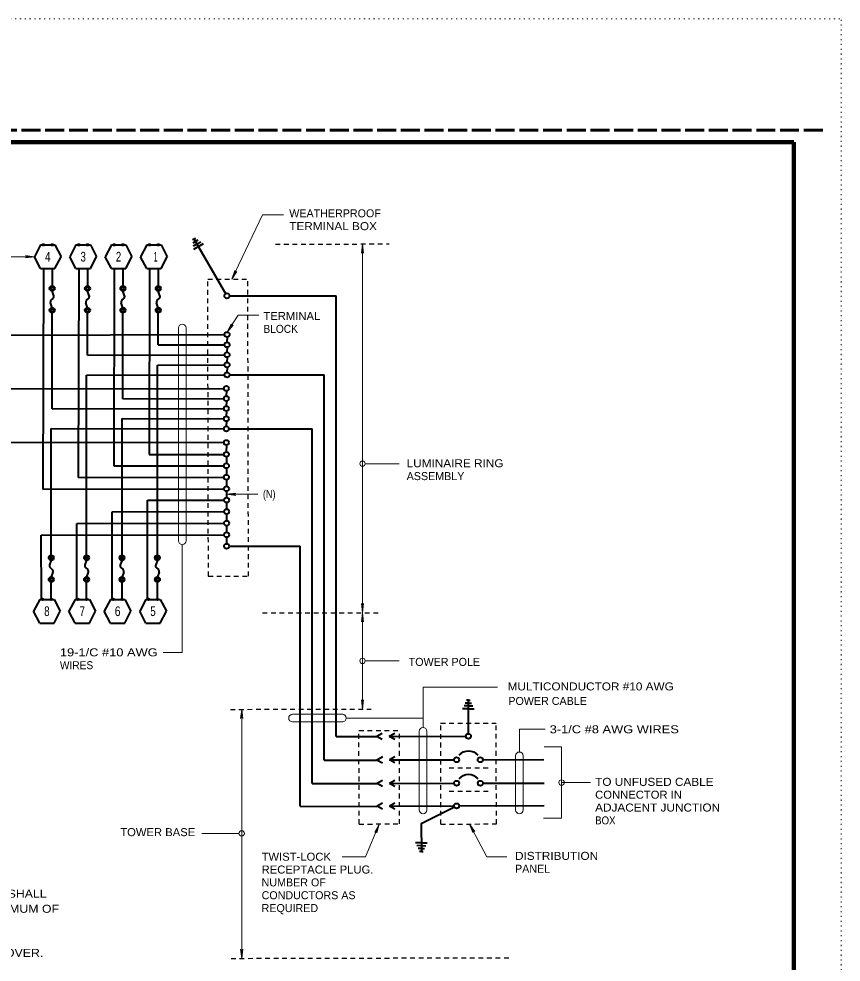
# Model space of a CAD drawing. Extents: x 312583 to 312854, y 144419 to 144597.
# Drawn here: x 312775.4 to 312853.5, y 144507.2 to 144596.8 of the extents above; entities that cross this region are included whole.
import ezdxf
from ezdxf.enums import TextEntityAlignment as Align

# ---------------------------------------------------------------- set-up
doc = ezdxf.new("R2010")
doc.units = 0
doc.header["$LTSCALE"] = 0.3
doc.header["$PDMODE"] = 32
doc.header["$PDSIZE"] = 0.15
for name, pattern in [('DOTTED', [1.5, 0.3, -1.2]), ('LONG_DASHED', [7.5, 6, -1.5]), ('SHORT_DASHED', [2.7, 1.5, -1.2])]:
    doc.linetypes.add(name, pattern=pattern)
for name, color, linetype, lineweight in [('1', 7, 'Continuous', 40), ('2', 7, 'Continuous', 13), ('62', 7, 'DOTTED', 13), ('63', 7, 'LONG_DASHED', 60)]:
    doc.layers.add(name, color=color, linetype=linetype, lineweight=lineweight)

msp = doc.modelspace()

# ---------------------------------------------------------------- linework, layer by layer
at = {"layer": '1', "lineweight": 158}
msp.add_line((312849, 144423.1446), (312849, 144585.0846), dxfattribs=at)
at = {"layer": '1'}
for p, q in [((312777.5006, 144575.328), (312776.918, 144574.201)), ((312777.5006, 144575.328), (312778.8653, 144575.328)), ((312778.8653, 144575.328), (312779.448, 144574.201)), ((312780.8586, 144575.328), (312780.276, 144574.201)), ((312780.8586, 144575.328), (312782.2233, 144575.328)), ((312782.2233, 144575.328), (312782.806, 144574.201)), ((312784.2166, 144575.328), (312783.634, 144574.201)), ((312784.2166, 144575.328), (312785.5813, 144575.328)), ((312785.5813, 144575.328), (312786.164, 144574.201)), ((312787.5746, 144575.328), (312786.992, 144574.201)), ((312787.5746, 144575.328), (312788.9393, 144575.328)), ((312788.9393, 144575.328), (312789.522, 144574.201)), ((312792.0826, 144575.88), (312791.9293, 144575.788)), ((312792.213, 144575.6576), (312791.9523, 144575.4966)), ((312792.351, 144575.4046), (312791.983, 144575.1976)), ((312792.489, 144575.1746), (312792.006, 144574.8986)), ((312792.0826, 144575.88), (312792.2283, 144575.9643)), ((312795.0726, 144570.6896), (312792.0826, 144575.88)), ((312792.213, 144575.6576), (312792.4736, 144575.788)), ((312792.3586, 144575.4123), (312792.719, 144575.6193)), ((312792.489, 144575.1746), (312792.9566, 144575.4506)), ((312777.5006, 144573.074), (312776.918, 144574.201)), ((312778.8653, 144573.074), (312779.448, 144574.201)), ((312780.8586, 144573.074), (312780.276, 144574.201)), ((312782.2233, 144573.074), (312782.806, 144574.201)), ((312784.2166, 144573.074), (312783.634, 144574.201)), ((312785.5813, 144573.074), (312786.164, 144574.201)), ((312787.5746, 144573.074), (312786.992, 144574.201)), ((312788.9393, 144573.074), (312789.522, 144574.201)), ((312777.5006, 144573.074), (312778.8653, 144573.074)), ((312777.769, 144573.074), (312777.7153, 144552.1363)), ((312778.597, 144573.074), (312778.597, 144571.4256)), ((312780.8586, 144573.074), (312782.2233, 144573.074)), ((312781.127, 144573.074), (312781.081, 144553.2326)), ((312781.955, 144573.074), (312781.955, 144571.4256)), ((312784.2166, 144573.074), (312785.5813, 144573.074)), ((312784.485, 144573.074), (312784.4466, 144554.329)), ((312785.313, 144573.074), (312785.313, 144571.4256)), ((312787.5746, 144573.074), (312788.9393, 144573.074)), ((312787.843, 144573.074), (312787.797, 144555.4253)), ((312788.671, 144573.074), (312788.671, 144571.4256)), ((312778.758, 144570.498), (312778.597, 144570.9503)), ((312782.116, 144570.498), (312781.955, 144570.9503)), ((312785.474, 144570.498), (312785.313, 144570.9503)), ((312788.832, 144570.498), (312788.671, 144570.9503)), ((312778.597, 144569.3556), (312778.436, 144569.808)), ((312778.4973, 144570.061), (312778.6966, 144570.245)), ((312781.955, 144569.3556), (312781.794, 144569.808)), ((312781.8553, 144570.061), (312782.0546, 144570.245)), ((312785.313, 144569.3556), (312785.152, 144569.808)), ((312785.2133, 144570.061), (312785.4126, 144570.245)), ((312788.671, 144569.3556), (312788.51, 144569.808)), ((312788.5713, 144570.061), (312788.7706, 144570.245)), ((312795.433, 144570.4826), (312805.576, 144570.498)), ((312805.576, 144528.6303), (312805.576, 144570.498)), ((312778.597, 144559.7493), (312778.597, 144568.8803)), ((312781.955, 144564.8553), (312781.955, 144568.8803)), ((312785.313, 144560.7076), (312785.313, 144568.8803)), ((312788.671, 144565.829), (312788.671, 144568.8803)), ((312770.7003, 144566.749), (312794.9653, 144566.8026)), ((312795.203, 144566.565), (312795.1953, 144566.082)), ((312788.671, 144565.829), (312794.9653, 144565.8443)), ((312795.203, 144565.6066), (312795.1953, 144565.1236)), ((312781.955, 144564.8553), (312794.9653, 144564.886)), ((312795.203, 144564.6483), (312795.1953, 144564.1653)), ((312788.5866, 144563.9123), (312794.9653, 144563.9276)), ((312788.5866, 144545.8573), (312788.5866, 144563.9123)), ((312795.203, 144563.69), (312795.1953, 144563.207)), ((312781.8706, 144562.9386), (312794.9653, 144562.9693)), ((312781.8706, 144545.8573), (312781.8706, 144562.9386)), ((312795.4406, 144562.9693), (312804.4336, 144562.9846)), ((312804.4336, 144526.3916), (312804.4336, 144562.9846)), ((312770.708, 144561.6353), (312794.8963, 144561.689)), ((312795.134, 144561.4513), (312795.1263, 144560.9683)), ((312785.313, 144560.7076), (312794.8963, 144560.7306)), ((312795.134, 144560.493), (312795.1263, 144560.01)), ((312778.597, 144559.7493), (312794.8963, 144559.7723)), ((312795.134, 144559.5346), (312795.1263, 144559.0516)), ((312785.2286, 144545.8573), (312785.2286, 144558.837)), ((312785.2286, 144558.837), (312794.8963, 144558.814)), ((312795.134, 144558.5763), (312795.1263, 144558.0933)), ((312778.5126, 144545.8573), (312778.5126, 144557.894)), ((312778.5126, 144557.894), (312794.8963, 144557.8556)), ((312795.3716, 144557.8556), (312803.2836, 144557.8633)), ((312803.2836, 144524.1683), (312803.2836, 144557.8633)), ((312770.616, 144556.5983), (312794.8963, 144556.5446)), ((312787.797, 144555.4253), (312794.904, 144555.433)), ((312795.134, 144556.307), (312795.1263, 144555.6706)), ((312795.1416, 144555.1953), (312795.134, 144554.559)), ((312784.4466, 144554.329), (312794.904, 144554.3443)), ((312795.1416, 144554.1066), (312795.134, 144553.4703)), ((312781.081, 144553.2326), (312794.904, 144553.2556)), ((312795.1416, 144553.018), (312795.134, 144552.3816)), ((312777.7153, 144552.1363), (312794.9116, 144552.167)), ((312795.1493, 144551.9293), (312795.1416, 144551.3236)), ((312787.636, 144551.0706), (312794.9193, 144551.086)), ((312787.659, 144541.6636), (312787.636, 144551.0706)), ((312795.157, 144550.8483), (312795.1493, 144550.212)), ((312784.2856, 144549.9743), (312794.9193, 144549.9896)), ((312784.301, 144541.6636), (312784.2856, 144549.9743)), ((312795.157, 144549.752), (312795.1493, 144549.1156)), ((312780.9276, 144548.8703), (312794.9193, 144548.8933)), ((312780.943, 144541.6636), (312780.9276, 144548.8703)), ((312795.157, 144548.6556), (312795.1493, 144548.0193)), ((312777.5696, 144547.7663), (312794.9193, 144547.797)), ((312777.585, 144541.6636), (312777.5696, 144547.7663)), ((312795.157, 144547.5593), (312795.1493, 144546.923)), ((312795.4866, 144546.7006), (312802.1336, 144546.7083)), ((312802.1336, 144522.014), (312802.1336, 144546.7083)), ((312778.5126, 144545.382), (312778.3516, 144544.9296)), ((312781.8706, 144545.382), (312781.7096, 144544.9296)), ((312785.2286, 144545.382), (312785.0676, 144544.9296)), ((312788.5866, 144545.382), (312788.4256, 144544.9296)), ((312778.413, 144544.6766), (312778.6123, 144544.4926)), ((312778.6736, 144544.2396), (312778.5126, 144543.7873)), ((312781.771, 144544.6766), (312781.9703, 144544.4926)), ((312782.0316, 144544.2396), (312781.8706, 144543.7873)), ((312785.129, 144544.6766), (312785.3283, 144544.4926)), ((312785.3896, 144544.2396), (312785.2286, 144543.7873)), ((312788.487, 144544.6766), (312788.6863, 144544.4926)), ((312788.7476, 144544.2396), (312788.5866, 144543.7873)), ((312778.5126, 144541.6636), (312778.5126, 144543.312)), ((312781.8706, 144541.6636), (312781.8706, 144543.312)), ((312785.2286, 144541.6636), (312785.2286, 144543.312)), ((312788.5866, 144541.6636), (312788.5866, 144543.312)), ((312777.4163, 144541.6636), (312776.8336, 144540.5366)), ((312777.4163, 144541.6636), (312778.781, 144541.6636)), ((312778.781, 144541.6636), (312779.3636, 144540.5366)), ((312780.7743, 144541.6636), (312780.1916, 144540.5366)), ((312780.7743, 144541.6636), (312782.139, 144541.6636)), ((312782.139, 144541.6636), (312782.7216, 144540.5366)), ((312784.1323, 144541.6636), (312783.5496, 144540.5366)), ((312784.1323, 144541.6636), (312785.497, 144541.6636)), ((312785.497, 144541.6636), (312786.0796, 144540.5366)), ((312787.4903, 144541.6636), (312786.9076, 144540.5366)), ((312787.4903, 144541.6636), (312788.855, 144541.6636)), ((312788.855, 144541.6636), (312789.4376, 144540.5366)), ((312777.4163, 144539.4096), (312776.8336, 144540.5366)), ((312778.781, 144539.4096), (312779.3636, 144540.5366)), ((312780.7743, 144539.4096), (312780.1916, 144540.5366)), ((312782.139, 144539.4096), (312782.7216, 144540.5366)), ((312784.1323, 144539.4096), (312783.5496, 144540.5366)), ((312785.497, 144539.4096), (312786.0796, 144540.5366)), ((312787.4903, 144539.4096), (312786.9076, 144540.5366)), ((312788.855, 144539.4096), (312789.4376, 144540.5366)), ((312777.4163, 144539.4096), (312778.781, 144539.4096)), ((312780.7743, 144539.4096), (312782.139, 144539.4096)), ((312784.1323, 144539.4096), (312785.497, 144539.4096)), ((312787.4903, 144539.4096), (312788.855, 144539.4096)), ((312818.1186, 144531.2676), (312817.5666, 144531.2753)), ((312818.111, 144531.536), (312817.697, 144531.5436)), ((312818.1186, 144531.8196), (312817.8196, 144531.812)), ((312818.1186, 144532.088), (312817.9423, 144532.0803)), ((312818.1186, 144528.8986), (312818.1186, 144532.088)), ((312818.1186, 144532.088), (312818.295, 144532.0803)), ((312818.1186, 144531.8196), (312818.4176, 144531.812)), ((312818.1186, 144531.2676), (312818.6706, 144531.2753)), ((312818.1263, 144531.536), (312818.5403, 144531.5436)), ((312805.576, 144528.6303), (312809.4246, 144528.638)), ((312809.9383, 144528.9293), (312809.4246, 144528.638)), ((312809.9383, 144528.3466), (312809.4246, 144528.638)), ((312811.119, 144528.937), (312810.6053, 144528.6456)), ((312810.6053, 144528.6456), (312817.881, 144528.661)), ((312811.119, 144528.3543), (312810.6053, 144528.6456)), ((312804.4336, 144526.3916), (312809.4323, 144526.407)), ((312809.946, 144526.6983), (312809.4323, 144526.407)), ((312809.946, 144526.1156), (312809.4323, 144526.407)), ((312811.1266, 144526.706), (312810.613, 144526.4146)), ((312810.613, 144526.4146), (312816.754, 144526.43)), ((312811.1266, 144526.1233), (312810.613, 144526.4146)), ((312819.4833, 144526.43), (312825.287, 144526.453)), ((312803.2836, 144524.1683), (312809.44, 144524.1836)), ((312809.9536, 144524.4673), (312809.44, 144524.176)), ((312809.9536, 144523.8846), (312809.44, 144524.176)), ((312811.1343, 144524.475), (312810.6206, 144524.1836)), ((312810.6206, 144524.1836), (312816.7616, 144524.199)), ((312811.1343, 144523.8923), (312810.6206, 144524.1836)), ((312819.491, 144524.199), (312825.2946, 144524.222)), ((312809.9536, 144522.313), (312809.44, 144522.0216)), ((312811.1343, 144522.3206), (312810.6206, 144522.0293)), ((312802.1336, 144522.014), (312809.4323, 144521.991)), ((312809.9536, 144521.7303), (312809.44, 144522.0216)), ((312810.6206, 144522.0293), (312816.7616, 144522.0446)), ((312811.1343, 144521.738), (312810.6206, 144522.0293)), ((312817.237, 144522.0446), (312825.31, 144522.0753)), ((312813.649, 144518.541), (312813.097, 144518.5333)), ((312813.6413, 144518.2726), (312813.2273, 144518.265)), ((312813.649, 144517.989), (312813.35, 144517.9966)), ((312813.649, 144518.541), (312814.201, 144518.5333)), ((312813.649, 144517.989), (312813.948, 144517.9966)), ((312813.6566, 144518.2726), (312814.0706, 144518.265)), ((312813.649, 144517.7206), (312813.4726, 144517.7283)), ((312813.649, 144517.7206), (312813.8253, 144517.7283))]:
    msp.add_line(p, q, dxfattribs=at)
at = {"layer": '1', "linetype": 'SHORT_DASHED', "lineweight": 25}
for p, q in [((312799.7953, 144575.3893), (312810.5823, 144575.4123)), ((312793.3706, 144572.062), (312797.1733, 144572.0696)), ((312793.432, 144543.864), (312793.3706, 144572.062)), ((312797.2346, 144543.8716), (312797.1733, 144572.0696)), ((312793.4243, 144543.864), (312797.227, 144543.8716)), ((312798.5686, 144540.368), (312809.7773, 144540.391)), ((312795.525, 144531.214), (312808.8726, 144531.2446)), ((312815.4813, 144529.8953), (312820.756, 144529.903)), ((312815.4966, 144520.3196), (312815.4813, 144529.8953)), ((312820.7713, 144520.335), (312820.756, 144529.903)), ((312807.7226, 144529.1976), (312811.5636, 144529.2053)), ((312807.738, 144520.3273), (312807.7226, 144529.1976)), ((312811.579, 144520.335), (312811.5636, 144529.2053)), ((312816.2863, 144525.6633), (312820.0046, 144525.6633)), ((312816.294, 144523.4323), (312820.0123, 144523.4323)), ((312807.738, 144520.3273), (312811.579, 144520.335)), ((312815.4966, 144520.3196), (312820.7713, 144520.335)), ((312795.5786, 144507.57), (312822.159, 144507.6313))]:
    msp.add_line(p, q, dxfattribs=at)
at = {"layer": '1', "lineweight": 158}
msp.add_lwpolyline([(312616.5, 144423.1446), (312616.5, 144585.0846), (312849, 144585.0846)], dxfattribs=at)
at = {"layer": '1'}
msp.add_lwpolyline([(312816.7846, 144521.9373), (312813.6413, 144520.358), (312813.649, 144517.7206)], dxfattribs=at)
for centre, radius in [((312778.597, 144571.188), 0.2396), ((312778.597, 144571.188), 0.1198), ((312781.955, 144571.188), 0.2396), ((312781.955, 144571.188), 0.1198), ((312785.313, 144571.188), 0.2396), ((312785.313, 144571.188), 0.1198), ((312788.671, 144571.188), 0.2396), ((312788.671, 144571.188), 0.1198), ((312795.1928, 144570.4855), 0.2396), ((312778.597, 144569.118), 0.2396), ((312778.597, 144569.118), 0.1198), ((312781.955, 144569.118), 0.2396), ((312781.955, 144569.118), 0.1198), ((312785.313, 144569.118), 0.2396), ((312785.313, 144569.118), 0.1198), ((312788.671, 144569.118), 0.2396), ((312788.671, 144569.118), 0.1198), ((312795.203, 144566.8026), 0.2396), ((312795.203, 144565.8443), 0.2396), ((312795.203, 144564.886), 0.2396), ((312795.203, 144563.9276), 0.2396), ((312795.203, 144562.9693), 0.2396), ((312795.134, 144561.689), 0.2396), ((312795.134, 144560.7306), 0.2396), ((312795.134, 144559.7723), 0.2396), ((312795.134, 144558.814), 0.2396), ((312795.134, 144557.8556), 0.2396), ((312795.134, 144556.5446), 0.2396), ((312795.1416, 144555.433), 0.2396), ((312795.1416, 144554.3443), 0.2396), ((312795.1416, 144553.2556), 0.2396), ((312795.1493, 144552.167), 0.2396), ((312795.157, 144551.086), 0.2396), ((312795.157, 144549.9896), 0.2396), ((312795.157, 144548.8933), 0.2396), ((312795.157, 144547.797), 0.2396), ((312795.157, 144546.7006), 0.2396), ((312778.5126, 144545.6196), 0.2396), ((312778.5126, 144545.6196), 0.1198), ((312781.8706, 144545.6196), 0.2396), ((312781.8706, 144545.6196), 0.1198), ((312785.2286, 144545.6196), 0.2396), ((312785.2286, 144545.6196), 0.1198), ((312788.5866, 144545.6196), 0.2396), ((312788.5866, 144545.6196), 0.1198), ((312778.5126, 144543.5496), 0.2396), ((312781.8706, 144543.5496), 0.2396), ((312785.2286, 144543.5496), 0.2396), ((312788.5866, 144543.5496), 0.2396), ((312778.5126, 144543.5496), 0.1198), ((312781.8706, 144543.5496), 0.1198), ((312785.2286, 144543.5496), 0.1198), ((312788.5866, 144543.5496), 0.1198), ((312818.1186, 144528.661), 0.2396), ((312816.9916, 144526.43), 0.2396), ((312819.2456, 144526.43), 0.2396), ((312816.9993, 144524.199), 0.2396), ((312819.2533, 144524.199), 0.2396), ((312816.9993, 144522.0446), 0.2396)]:
    msp.add_circle(centre, radius, dxfattribs=at)
for centre, radius, start, end in [((312778.6612, 144569.8857), 0.2396, 132.8789, 199.74684), ((312778.5326, 144570.4204), 0.2396, 312.82526, 19.74684), ((312782.0192, 144569.8857), 0.2396, 132.8789, 199.74684), ((312781.8906, 144570.4204), 0.2396, 312.82526, 19.74684), ((312785.3772, 144569.8857), 0.2396, 132.8789, 199.74684), ((312785.2486, 144570.4204), 0.2396, 312.82526, 19.74684), ((312788.7352, 144569.8857), 0.2396, 132.8789, 199.74684), ((312788.6066, 144570.4204), 0.2396, 312.82526, 19.74684), ((312778.5769, 144544.8519), 0.2396, 160.25316, 227.1211), ((312781.9349, 144544.8519), 0.2396, 160.25316, 227.1211), ((312785.2929, 144544.8519), 0.2396, 160.25316, 227.1211), ((312788.6509, 144544.8519), 0.2396, 160.25316, 227.1211), ((312778.4483, 144544.3172), 0.2396, 340.25316, 47.17474), ((312781.8063, 144544.3172), 0.2396, 340.25316, 47.17474), ((312785.1643, 144544.3172), 0.2396, 340.25316, 47.17474), ((312788.5223, 144544.3172), 0.2396, 340.25316, 47.17474), ((312818.1186, 144525.9717), 1.2786, 43.48857, 136.51143), ((312818.1263, 144523.7407), 1.2786, 43.48857, 136.51143)]:
    msp.add_arc(centre, radius, start, end, dxfattribs=at)
for p in [(312777.769, 144575.328), (312778.597, 144575.328), (312781.127, 144575.328), (312781.955, 144575.328), (312784.485, 144575.328), (312785.313, 144575.328), (312787.843, 144575.328), (312788.671, 144575.328), (312777.6846, 144541.6636), (312778.5126, 144541.6636), (312781.0426, 144541.6636), (312781.8706, 144541.6636), (312784.4006, 144541.6636), (312785.2286, 144541.6636), (312787.7586, 144541.6636), (312788.5866, 144541.6636)]:
    msp.add_point(p, dxfattribs=at)
at = {"layer": '2'}
for p, q in [((312798.5686, 144578.1876), (312795.663, 144572.0696)), ((312798.5686, 144578.1876), (312800.5466, 144578.1876)), ((312808.06, 144575.4123), (312807.9526, 144574.546)), ((312808.06, 144540.391), (312808.06, 144575.4123)), ((312808.06, 144575.4123), (312808.1673, 144574.546)), ((312776.0516, 144574.3083), (312776.3276, 144574.201)), ((312776.918, 144574.201), (312776.0516, 144574.3083)), ((312807.9526, 144574.546), (312808.06, 144574.822)), ((312808.1673, 144574.546), (312808.06, 144574.822)), ((312773.33, 144574.201), (312776.918, 144574.201)), ((312776.0516, 144574.0936), (312776.3276, 144574.201)), ((312776.918, 144574.201), (312776.0516, 144574.0936)), ((312795.663, 144572.0696), (312795.939, 144572.8976)), ((312795.663, 144572.0696), (312796.1306, 144572.8056)), ((312795.939, 144572.8976), (312795.916, 144572.6063)), ((312796.1306, 144572.8056), (312795.916, 144572.6063)), ((312796.2456, 144568.635), (312795.203, 144567.0403)), ((312796.2456, 144568.635), (312798.2236, 144568.635)), ((312790.5876, 144547.2296), (312790.5876, 144567.4313)), ((312791.3083, 144547.2296), (312791.3083, 144567.4313)), ((312795.203, 144567.0403), (312795.5863, 144567.8223)), ((312795.203, 144567.0403), (312795.7703, 144567.7073)), ((312795.5863, 144567.8223), (312795.525, 144567.531)), ((312795.7703, 144567.7073), (312795.525, 144567.531)), ((312808.313, 144554.5436), (312811.5406, 144554.5436)), ((312795.157, 144551.638), (312796.0233, 144551.7453)), ((312795.157, 144551.638), (312798.1393, 144551.638)), ((312795.157, 144551.638), (312796.0233, 144551.5306)), ((312796.0233, 144551.7453), (312795.7473, 144551.638)), ((312796.0233, 144551.5306), (312795.7473, 144551.638)), ((312790.948, 144536.6036), (312790.948, 144546.8693)), ((312807.9526, 144541.2573), (312808.06, 144540.9813)), ((312808.06, 144540.391), (312807.9526, 144541.2573)), ((312808.1673, 144541.2573), (312808.06, 144540.9813)), ((312808.06, 144540.391), (312808.1673, 144541.2573)), ((312808.06, 144540.391), (312807.9526, 144539.5246)), ((312808.06, 144540.391), (312808.1673, 144539.5246)), ((312808.06, 144531.2446), (312808.06, 144540.391)), ((312807.9526, 144539.5246), (312808.06, 144539.8006)), ((312808.1673, 144539.5246), (312808.06, 144539.8006)), ((312789.1386, 144536.6036), (312790.948, 144536.6036)), ((312808.313, 144535.8216), (312811.5406, 144535.8216)), ((312813.81, 144529.489), (312813.81, 144533.3376)), ((312813.81, 144533.3376), (312820.8633, 144533.3376)), ((312807.9526, 144532.111), (312808.06, 144531.835)), ((312808.06, 144531.2446), (312807.9526, 144532.111)), ((312808.1673, 144532.111), (312808.06, 144531.835)), ((312808.06, 144531.2446), (312808.1673, 144532.111)), ((312796.5906, 144531.214), (312796.4833, 144530.3476)), ((312796.4833, 144530.3476), (312796.5906, 144530.6236)), ((312796.5906, 144507.57), (312796.5906, 144531.214)), ((312796.5906, 144531.214), (312796.698, 144530.3476)), ((312796.698, 144530.3476), (312796.5906, 144530.6236)), ((312801.413, 144530.7463), (312806.197, 144530.7463)), ((312806.5113, 144530.386), (312813.81, 144530.386)), ((312801.413, 144530.0256), (312806.197, 144530.0256)), ((312813.4496, 144521.669), (312813.4496, 144529.1286)), ((312814.1703, 144521.669), (312814.1703, 144529.1286)), ((312822.596, 144521.669), (312822.596, 144526.8056)), ((312823.3166, 144521.669), (312823.3166, 144526.8056)), ((312825.31, 144527.649), (312826.9583, 144527.649)), ((312826.9583, 144520.8793), (312826.9583, 144527.649)), ((312826.9583, 144524.268), (312829.6953, 144524.268)), ((312825.2486, 144520.8793), (312826.9583, 144520.8793)), ((312809.6546, 144520.3273), (312809.2253, 144519.5683)), ((312809.2253, 144519.5683), (312809.4246, 144519.783)), ((312809.6546, 144520.3273), (312809.417, 144519.484)), ((312809.417, 144519.484), (312809.4246, 144519.783)), ((312819.8743, 144517.207), (312818.2183, 144520.3273)), ((312818.2183, 144520.3273), (312818.5326, 144519.5146)), ((312818.2183, 144520.3273), (312818.7166, 144519.6143)), ((312818.5326, 144519.5146), (312818.4943, 144519.806)), ((312818.7166, 144519.6143), (312818.4943, 144519.806)), ((312792.8033, 144519.438), (312796.3376, 144519.438)), ((312819.8743, 144517.207), (312821.768, 144517.207)), ((312796.4833, 144508.4363), (312796.5906, 144508.1603)), ((312796.5906, 144507.57), (312796.4833, 144508.4363)), ((312796.698, 144508.4363), (312796.5906, 144508.1603)), ((312796.5906, 144507.57), (312796.698, 144508.4363))]:
    msp.add_line(p, q, dxfattribs=at)
for points in [[(312822.9563, 144527.166), (312822.9563, 144529.328), (312825.3943, 144529.328)], [(312806.128, 144517.207), (312808.3513, 144517.207), (312809.6546, 144520.3273)]]:
    msp.add_lwpolyline(points, dxfattribs=at)
for centre in [(312808.06, 144554.5436), (312808.06, 144535.8216), (312826.9583, 144524.268), (312796.5906, 144519.438)]:
    msp.add_circle(centre, 0.2554, dxfattribs=at)
for centre, start, end in [((312790.948, 144567.4313), 0, 180), ((312790.948, 144547.2296), 180, 0), ((312801.413, 144530.386), 90, 270), ((312806.151, 144530.386), 270, 90), ((312813.81, 144529.1286), 0, 180), ((312822.9563, 144526.8056), 0, 180), ((312813.81, 144521.669), 180, 0), ((312822.9563, 144521.669), 180, 0)]:
    msp.add_arc(centre, 0.3603, start, end, dxfattribs=at)
at = {"layer": '62'}
msp.add_line((312601.2, 144596.7846), (312853.5, 144596.7846), dxfattribs=at)
msp.add_lwpolyline([(312601.2, 144418.5846), (312853.5, 144418.5846), (312853.5, 144596.7846)], dxfattribs=at)
at = {"layer": '63'}
msp.add_line((312851.75, 144586.2246), (312583.526, 144586.2246), dxfattribs=at)

# ---------------------------------------------------------------- texts
at = {"layer": '2'}
for s, p in [('WEATHERPROOF', (312801.1063, 144577.9413)), ('ASSEMBLY', (312812.2536, 144552.9853)), ('TOWER POLE', (312812.4445, 144535.3434)), ('POWER CABLE', (312821.9068, 144531.6346)), ('PANEL', (312822.5423, 144515.7023)), ('NUMBER OF', (312798.4817, 144514.4056)), ('CONDUCTORS AS', (312798.4817, 144513.1856)), ('REQUIRED', (312798.4817, 144511.9656))]:
    msp.add_text(s, height=0.76, dxfattribs=at).set_placement(p)
for s, width, p in [('TERMINAL BOX', 1.1, (312801.1063, 144576.7213)), ('TERMINAL', 1.05, (312798.653, 144568.1893)), ('BLOCK', 0.95, (312798.653, 144566.9693)), ('LUMINAIRE RING', 1.1, (312812.2536, 144554.2053)), ('19-1/C #10 AWG', 1.2, (312779.3325, 144536.25)), ('WIRES', 0.95, (312779.3325, 144535.03)), ('MULTICONDUCTOR #10 AWG', 1.1, (312821.8367, 144533.0146)), ('3-1/C #8 AWG WIRES', 1.2, (312825.8305, 144528.9436)), ('TO UNFUSED CABLE', 1.1, (312830.1476, 144523.9526)), ('CONNECTOR IN', 1.05, (312830.1476, 144522.7326)), ('ADJACENT JUNCTION', 1.1, (312830.1476, 144521.5126)), ('BOX', 0.9, (312830.1476, 144520.2926)), ('TOWER BASE', 1.05, (312785.0637, 144519.1763)), ('TWIST-LOCK', 1.05, (312798.4817, 144516.8456)), ('DISTRIBUTION', 1.1, (312822.5423, 144516.9223)), ('RECEPTACLE PLUG.', 1.05, (312798.4817, 144515.6256)), ('THE LUMINAIRE RING ASSEMBLY AND SUPPORT ASSEMBLY SHALL', 1.15, (312739.7554, 144513.3343)), ('BE PROVIDED WITH SUITABLE POSITIONING DEVICES.  (MINIMUM OF', 1.15, (312739.9657, 144511.9006)), ('HEAD ASSEMBLY WILL BE PROVIDED WITH AN ALUMINUM COVER.', 1.15, (312739.8956, 144507.7146))]:
    msp.add_text(s, height=0.76, dxfattribs=dict(at, width=width)).set_placement(p)
for s, height, width, p in [('4', 0.92, 0.75, (312778.1829, 144573.741)), ('3', 0.92, 0.75, (312781.5409, 144573.741)), ('2', 0.92, 0.75, (312784.899, 144573.741)), ('1', 0.92, 0.5, (312788.4256, 144573.741)), ('(N)', 0.76, 0.85, (312799.2058, 144551.2766)), ('8', 0.92, 0.75, (312778.0986, 144540.0766)), ('7', 0.92, 0.75, (312781.4567, 144540.0766)), ('6', 0.92, 0.8, (312784.8147, 144540.0766)), ('5', 0.92, 0.75, (312788.1727, 144540.0766))]:
    msp.add_text(s, height=height, dxfattribs=dict(at, width=width)).set_placement(p, align=Align.CENTER)

doc.saveas('drawing.dxf')
